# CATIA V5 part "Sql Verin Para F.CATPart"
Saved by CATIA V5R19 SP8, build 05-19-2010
Part number: Sql Verin Para F
Publications: "Droite.1", "Point.3", "Plan.1"
Bounding box of the stored display mesh (mm): x 0 to 0, y -120 to 470, z -700 to -425
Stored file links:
  G:\EU_thinkMotion\CFAO_2010\MMS_groupe3\MMS_groupe3\rdalborgo\rdalborgo\Sql Verin Para F.CATPart
  G:\EU_thinkMotion\CFAO_2010\MMS_groupe3\MMS_groupe3\rdalborgo\rdalborgo\rdalborgo.CATProduct
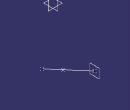
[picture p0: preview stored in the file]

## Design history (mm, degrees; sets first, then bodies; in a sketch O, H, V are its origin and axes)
Set1
  Point1 "B verin para": linked copy from another document
  Point2 "A verin para": linked copy from another document
  Plane1: linked copy from another document
Set2
  Line1: type PtPt, FirstPoint Point1, SecondPoint Point2
  Point3: type OnCurve, Support Line1, Ratio 0.4
  Plane2: type OffsetPt, RefPlane Plane1, RefPoint Point2
Body1 (main body)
